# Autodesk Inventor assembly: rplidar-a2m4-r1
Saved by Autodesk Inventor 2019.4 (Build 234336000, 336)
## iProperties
Created: 2020-05
Part Number: rplidar-a2m4-r1
Document SubType Name: Assembly
Designer: Administrator
Title: rplidar-a2m4-r1 v2
Author: Administrator
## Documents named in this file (2)
- c:\worker\convert-fusion-r04\tmp\job-1\3\output\files\88492291-068e-4573-82a5-cdd8cfb136cd\rplidar-a2m4-r1 v2.iam
- c:\worker\convert-fusion-r04\tmp\job-1\3\output\files\88492291-068e-4573-82a5-cdd8cfb136cd\rplidar-a2m4-r1.iam
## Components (1 placed, 1 different names)
1. rplidar-a2m4-r1:1 [sub-assembly]
